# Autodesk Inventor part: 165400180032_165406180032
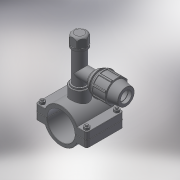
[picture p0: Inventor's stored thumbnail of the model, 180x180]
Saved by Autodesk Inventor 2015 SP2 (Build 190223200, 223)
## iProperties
Created: 2017-05
Part Number: 165400180032_165406180032
Material: Generic
Description: PLASSON TAPPER FOR PE+PVC PIPE 180-32
Document SubType Name: Modeling
Designer: KIM
Density: 1 g/cm^3
Appearance: Default
Author: KIM
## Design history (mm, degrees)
derived "16540.ipt"
feature "Solid1::16540.ipt"
feature "Solid2::16540.ipt"
tag "TaggingFeature1"
body "Solid1"
other parameters: "d0" = 198, "d1" = 245, "d4" = 154, "d5" = 0, "d6" = 12.25, "d7" = 245, "d8" = 0.1, "d10" = 0, "d11" = 1.8, "d14" = 50.6376, "d20" = 1.8, "d23" = 1.8, "d36" = 15, "d37" = 12, "d38" = 98, "d39" = 0, "d40" = 3, "d41" = 5, "d42" = 0, "d44" = 3, "d45" = 0, "d46" = 1.8, "d51" = 127, "d52" = 38.952, "d53" = 25, "d54" = 0, "d55" = 32, "d57" = 0, "d58" = 194.4, "d60" = 0, "d62" = 15, "d63" = 12, "d67" = 32, "d68" = 9.08333, "d69" = 21.8, "d70" = 64, "d71" = 48, "d72" = 1.55714, "d73" = 51.2, "d74" = 120 deg, "d75" = 48, "d76" = 10 deg, "d77" = 57.6, "d78" = 32.7, "d79" = 71, "d80" = 25.6, "d81" = 109, "d82" = 7.1, "d87" = 15.57143, "d90" = 59.52, "d91" = 35 deg, "d92" = 17.5 deg, "d94" = 0, "d96" = 360 deg, "d98" = 0.64, "d99" = 78.1, "d100" = 35.0568, "d101" = 135 deg, "d102" = 1.28, "d105" = 3.2, "d106" = 0, "d107" = 0.1, "d108" = 35.0568, "d109" = 42.8472, "d111" = 26.6, "d112" = 6.65, "d113" = 3.63333, "d116" = 0, "d117" = 38, "d118" = 21.8, "d119" = 0, "d121" = 133, "B_" = 32, "G_" = 38.952, "A_" = 127, "L_" = 245, "L_1" = 154, "l_2" = 25, "d_1" = 32, "E_" = 64, "l_" = 71, "H_" = 109, "H_2" = 133
